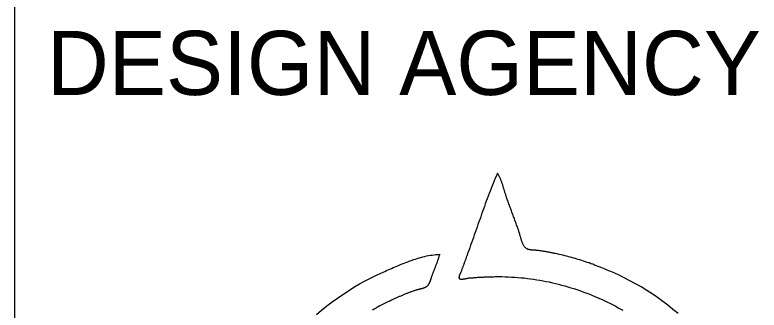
# Model space of a CAD drawing. Extents: x 0 to 34, y 0 to 22.
# Drawn here: x 32 to 33.162, y 4.514 to 4.975 of the extents above; entities that cross this region are included whole.
import ezdxf

# ---------------------------------------------------------------- set-up
doc = ezdxf.new("R2010")
doc.units = 0
for name, color, linetype in [('SH_Border', 7, 'Continuous'), ('SH_Data', 7, 'Continuous'), ('SH_Text', 7, 'Continuous')]:
    doc.layers.add(name, color=color, linetype=linetype)

msp = doc.modelspace()

# ---------------------------------------------------------------- linework, layer by layer
at = {"layer": 'SH_Border'}
msp.add_line((32, 0.5), (32, 21.5), dxfattribs=at)
at = {"layer": 'SH_Text'}
for points in [[(32.7532, 4.7277), (32.7515, 4.7238), (32.7498, 4.7199), (32.7481, 4.716), (32.7466, 4.712), (32.745, 4.708), (32.7434, 4.7041), (32.7418, 4.7001), (32.7403, 4.6961), (32.7387, 4.6921), (32.7372, 4.6881), (32.7357, 4.6841), (32.7342, 4.6801), (32.7328, 4.676), (32.7313, 4.672), (32.7298, 4.668), (32.7284, 4.6639), (32.7271, 4.6599), (32.7256, 4.6558), (32.7241, 4.6518), (32.7227, 4.6478), (32.7214, 4.6436), (32.7199, 4.6396), (32.7184, 4.6355), (32.7171, 4.6315), (32.7157, 4.6275), (32.7142, 4.6235), (32.7129, 4.6194), (32.7114, 4.6154), (32.71, 4.6114), (32.7085, 4.6074), (32.707, 4.6035)], [(32.7656, 4.6959), (32.7652, 4.6969), (32.7649, 4.6978), (32.7646, 4.6988), (32.7643, 4.6998), (32.764, 4.7009), (32.7637, 4.702), (32.7633, 4.7031), (32.7631, 4.7041), (32.7627, 4.7051), (32.7623, 4.7063), (32.7621, 4.7074), (32.7617, 4.7085), (32.7614, 4.7096), (32.761, 4.7107), (32.7606, 4.7118), (32.7603, 4.7129), (32.7599, 4.714), (32.7595, 4.7151), (32.7592, 4.7161), (32.7587, 4.7172), (32.7583, 4.7182), (32.7578, 4.7193), (32.7575, 4.7203), (32.757, 4.7214), (32.7565, 4.7223), (32.756, 4.7233), (32.7555, 4.7242), (32.7549, 4.7251), (32.7545, 4.726), (32.7538, 4.7268), (32.7532, 4.7277)], [(32.7856, 4.6404), (32.785, 4.6422), (32.7844, 4.644), (32.7837, 4.6457), (32.7831, 4.6475), (32.7823, 4.6493), (32.7817, 4.6512), (32.781, 4.6529), (32.7804, 4.6547), (32.7797, 4.6565), (32.7791, 4.6582), (32.7783, 4.66), (32.7777, 4.6618), (32.777, 4.6637), (32.7764, 4.6654), (32.7758, 4.6672), (32.7751, 4.669), (32.7745, 4.6708), (32.7739, 4.6725), (32.7731, 4.6743), (32.7725, 4.6761), (32.7719, 4.678), (32.7712, 4.6797), (32.7706, 4.6815), (32.77, 4.6833), (32.7694, 4.6851), (32.7686, 4.6869), (32.768, 4.6886), (32.7674, 4.6904), (32.7668, 4.6923), (32.7662, 4.6941), (32.7656, 4.6959)], [(32.7979, 4.6106), (32.7973, 4.6112), (32.7966, 4.6118), (32.796, 4.6124), (32.7954, 4.6131), (32.7949, 4.6138), (32.7943, 4.6147), (32.7939, 4.6156), (32.7934, 4.6165), (32.7929, 4.6175), (32.7925, 4.6186), (32.792, 4.6195), (32.7917, 4.6206), (32.7913, 4.6217), (32.7908, 4.6228), (32.7905, 4.6239), (32.7901, 4.6251), (32.7899, 4.6262), (32.7895, 4.6274), (32.7891, 4.6285), (32.7889, 4.6296), (32.7885, 4.6308), (32.7882, 4.6319), (32.7879, 4.633), (32.7877, 4.6341), (32.7873, 4.635), (32.7871, 4.636), (32.7868, 4.637), (32.7865, 4.638), (32.7862, 4.6388), (32.786, 4.6396), (32.7856, 4.6404)], [(32.5747, 4.5736), (32.5772, 4.5747), (32.5799, 4.5759), (32.5825, 4.577), (32.5852, 4.5782), (32.5879, 4.5794), (32.5907, 4.5806), (32.5934, 4.5818), (32.5962, 4.5829), (32.599, 4.5841), (32.6018, 4.5853), (32.6047, 4.5864), (32.6075, 4.5876), (32.6104, 4.5887), (32.6133, 4.5898), (32.6162, 4.5909), (32.6192, 4.5919), (32.6221, 4.593), (32.6251, 4.5938), (32.628, 4.5948), (32.6309, 4.5956), (32.6338, 4.5965), (32.6369, 4.5973), (32.6398, 4.5981), (32.6427, 4.5987), (32.6456, 4.5993), (32.6485, 4.5998), (32.6514, 4.6002), (32.6543, 4.6007), (32.6572, 4.601), (32.6601, 4.6012), (32.6629, 4.6015)], [(32.6629, 4.6015), (32.6626, 4.6002), (32.6623, 4.5992), (32.6619, 4.5979), (32.6616, 4.5969), (32.6612, 4.5958), (32.6609, 4.5945), (32.6605, 4.5935), (32.6601, 4.5922), (32.6596, 4.5912), (32.6593, 4.5901), (32.6589, 4.5888), (32.6584, 4.5878), (32.6581, 4.5867), (32.6576, 4.5856), (32.6572, 4.5844), (32.6567, 4.5833), (32.6564, 4.5822), (32.6559, 4.5811), (32.6555, 4.5799), (32.655, 4.5788), (32.6546, 4.5777), (32.6542, 4.5766), (32.6537, 4.5754), (32.6532, 4.5743), (32.6529, 4.5732), (32.6524, 4.5721), (32.652, 4.571), (32.6515, 4.5698), (32.6512, 4.5687), (32.6507, 4.5676), (32.6503, 4.5665)], [(32.707, 4.6035), (32.7067, 4.6025), (32.7063, 4.6016), (32.7061, 4.6006), (32.7057, 4.5996), (32.7054, 4.5987), (32.705, 4.5977), (32.7046, 4.5967), (32.7043, 4.5958), (32.7039, 4.5948), (32.7037, 4.5938), (32.7033, 4.5928), (32.7029, 4.592), (32.7026, 4.591), (32.7022, 4.5901), (32.7018, 4.5891), (32.7015, 4.5881), (32.7011, 4.5872), (32.7007, 4.5862), (32.7005, 4.5852), (32.7001, 4.5842), (32.6998, 4.5833), (32.6994, 4.5823), (32.699, 4.5813), (32.6987, 4.5804), (32.6983, 4.5795), (32.698, 4.5785), (32.6976, 4.5776), (32.6972, 4.5766), (32.6969, 4.5756), (32.6965, 4.5747), (32.6963, 4.5737)], [(32.8139, 4.6075), (32.8134, 4.6075), (32.8129, 4.6076), (32.8124, 4.6076), (32.8119, 4.6076), (32.8114, 4.6078), (32.8108, 4.6078), (32.8103, 4.6078), (32.8097, 4.6078), (32.8093, 4.6079), (32.8086, 4.6079), (32.808, 4.6079), (32.8076, 4.6079), (32.807, 4.608), (32.8063, 4.608), (32.8059, 4.6081), (32.8053, 4.6081), (32.8046, 4.6082), (32.8042, 4.6082), (32.8036, 4.6084), (32.8031, 4.6085), (32.8025, 4.6086), (32.802, 4.6087), (32.8015, 4.6089), (32.8009, 4.609), (32.8004, 4.6092), (32.7999, 4.6093), (32.7996, 4.6096), (32.7991, 4.6098), (32.7986, 4.6101), (32.7982, 4.6103), (32.7979, 4.6106)], [(32.8436, 4.6024), (32.8426, 4.6027), (32.8417, 4.6028), (32.8408, 4.603), (32.8398, 4.6033), (32.8388, 4.6034), (32.8379, 4.6036), (32.8369, 4.6038), (32.8359, 4.604), (32.835, 4.6041), (32.8341, 4.6044), (32.8331, 4.6045), (32.8322, 4.6047), (32.8312, 4.6049), (32.8302, 4.6051), (32.8293, 4.6052), (32.8283, 4.6055), (32.8273, 4.6056), (32.8263, 4.6057), (32.8254, 4.6059), (32.8244, 4.6061), (32.8234, 4.6062), (32.8225, 4.6063), (32.8215, 4.6065), (32.8205, 4.6067), (32.8196, 4.6068), (32.8186, 4.6069), (32.8177, 4.607), (32.8168, 4.6072), (32.8158, 4.6073), (32.8148, 4.6074), (32.8139, 4.6075)], [(32.9329, 4.5732), (32.9301, 4.5744), (32.9273, 4.5756), (32.9246, 4.5768), (32.9216, 4.5781), (32.9189, 4.5791), (32.9161, 4.5802), (32.9133, 4.5815), (32.9104, 4.5825), (32.9076, 4.5835), (32.9048, 4.5846), (32.9019, 4.5857), (32.8991, 4.5867), (32.8962, 4.5878), (32.8933, 4.5887), (32.8905, 4.5897), (32.8876, 4.5907), (32.8847, 4.5915), (32.8818, 4.5925), (32.8788, 4.5933), (32.8759, 4.5943), (32.873, 4.5952), (32.8701, 4.596), (32.8672, 4.5967), (32.8643, 4.5976), (32.8614, 4.5983), (32.8584, 4.599), (32.8554, 4.5998), (32.8525, 4.6005), (32.8495, 4.6012), (32.8466, 4.6018), (32.8436, 4.6024)], [(32.4709, 4.5076), (32.4788, 4.5143), (32.4868, 4.5207), (32.495, 4.5269), (32.5034, 4.533), (32.5119, 4.5388), (32.5205, 4.5445), (32.5292, 4.5498), (32.538, 4.555), (32.547, 4.56), (32.5561, 4.5647), (32.5653, 4.5693), (32.5747, 4.5736)], [(32.6503, 4.5665), (32.6501, 4.5661), (32.6499, 4.5656), (32.6498, 4.5652), (32.6496, 4.5647), (32.6495, 4.5642), (32.6493, 4.5638), (32.6492, 4.5631), (32.649, 4.5627), (32.6489, 4.5622), (32.6487, 4.5617), (32.6485, 4.5611), (32.6484, 4.5606), (32.6481, 4.5601), (32.648, 4.5595), (32.6478, 4.559), (32.6476, 4.5585), (32.6474, 4.5579), (32.6473, 4.5574), (32.647, 4.557), (32.6468, 4.5565), (32.6466, 4.556), (32.6463, 4.5555), (32.6461, 4.555), (32.6458, 4.5545), (32.6456, 4.5542), (32.6453, 4.5537), (32.6451, 4.5533), (32.6447, 4.553), (32.6445, 4.5525), (32.6441, 4.5521), (32.6438, 4.5519)], [(32.6963, 4.5737), (32.6961, 4.5735), (32.696, 4.5732), (32.6959, 4.573), (32.6958, 4.5727), (32.6957, 4.5724), (32.6955, 4.5721), (32.6954, 4.5718), (32.6952, 4.5714), (32.695, 4.571), (32.6949, 4.5707), (32.6947, 4.5703), (32.6946, 4.5699), (32.6944, 4.5696), (32.6942, 4.5691), (32.6941, 4.5687), (32.694, 4.5684), (32.6938, 4.568), (32.6937, 4.5675), (32.6936, 4.5671), (32.6935, 4.5668), (32.6935, 4.5664), (32.6933, 4.5661), (32.6933, 4.5657), (32.6932, 4.5653), (32.6932, 4.565), (32.6932, 4.5647), (32.6933, 4.5644), (32.6933, 4.5641), (32.6935, 4.5639), (32.6936, 4.5636), (32.6937, 4.5634)], [(32.7091, 4.5644), (32.7106, 4.5645), (32.7121, 4.5646), (32.7136, 4.5647), (32.7151, 4.5648), (32.7166, 4.565), (32.7181, 4.5651), (32.7195, 4.5652), (32.721, 4.5653), (32.7226, 4.5654), (32.724, 4.5656), (32.7255, 4.5657), (32.7269, 4.5657), (32.7285, 4.5658), (32.73, 4.5659), (32.7314, 4.5659), (32.7329, 4.5661), (32.7344, 4.5661), (32.7359, 4.5662), (32.7374, 4.5662), (32.7388, 4.5663), (32.7404, 4.5663), (32.7418, 4.5663), (32.7433, 4.5664), (32.7449, 4.5664), (32.7463, 4.5664), (32.7478, 4.5664), (32.7494, 4.5665), (32.7508, 4.5665), (32.7523, 4.5665), (32.7538, 4.5665), (32.7553, 4.5665)], [(32.7553, 4.5665), (32.7603, 4.5665), (32.7652, 4.5664), (32.7702, 4.5662), (32.7752, 4.5659), (32.7802, 4.5657), (32.785, 4.5653), (32.79, 4.5648), (32.7949, 4.5644), (32.7999, 4.5638), (32.8048, 4.5631), (32.8097, 4.5624), (32.8146, 4.5617), (32.8196, 4.5608), (32.8244, 4.56), (32.8293, 4.559), (32.8341, 4.5581), (32.839, 4.557), (32.8438, 4.5558), (32.8487, 4.5547), (32.8534, 4.5533), (32.8582, 4.552), (32.863, 4.5507), (32.8678, 4.5492), (32.8725, 4.5477), (32.8773, 4.5462), (32.882, 4.5446), (32.8866, 4.5429), (32.8913, 4.5412), (32.8959, 4.5394), (32.9005, 4.5376), (32.9052, 4.5357)], [(33.0351, 4.5088), (33.0272, 4.5154), (33.0194, 4.5217), (33.0112, 4.5277), (33.0031, 4.5337), (32.9947, 4.5394), (32.9863, 4.545), (32.9777, 4.5503), (32.9689, 4.5553), (32.9601, 4.5601), (32.9511, 4.5647), (32.942, 4.5691), (32.9329, 4.5732)], [(32.6937, 4.5634), (32.694, 4.5633), (32.6942, 4.563), (32.6946, 4.5629), (32.6949, 4.5628), (32.6954, 4.5627), (32.6958, 4.5627), (32.6963, 4.5625), (32.6967, 4.5625), (32.6973, 4.5625), (32.6978, 4.5625), (32.6984, 4.5625), (32.699, 4.5627), (32.6997, 4.5627), (32.7003, 4.5628), (32.7009, 4.5629), (32.7015, 4.563), (32.7021, 4.563), (32.7027, 4.5631), (32.7033, 4.5633), (32.7039, 4.5634), (32.7045, 4.5635), (32.705, 4.5636), (32.7056, 4.5638), (32.7062, 4.5639), (32.7067, 4.564), (32.7072, 4.5641), (32.7077, 4.5641), (32.708, 4.5642), (32.7085, 4.5644), (32.7087, 4.5644), (32.7091, 4.5644)], [(32.6259, 4.5453), (32.6248, 4.545), (32.6236, 4.5445), (32.6225, 4.5441), (32.6213, 4.5437), (32.6202, 4.5433), (32.6192, 4.5429), (32.6179, 4.5425), (32.6168, 4.5421), (32.6156, 4.5417), (32.6145, 4.5412), (32.6135, 4.5407), (32.6122, 4.5404), (32.6111, 4.5399), (32.6101, 4.5394), (32.6088, 4.539), (32.6078, 4.5385), (32.6067, 4.538), (32.6055, 4.5376), (32.6044, 4.5372), (32.6033, 4.5367), (32.6022, 4.5362), (32.601, 4.5357), (32.5999, 4.5353), (32.5988, 4.5348), (32.5977, 4.5343), (32.5966, 4.5338), (32.5955, 4.5333), (32.5944, 4.5328), (32.5932, 4.5324), (32.5921, 4.5317), (32.591, 4.5313)], [(32.6438, 4.5519), (32.6434, 4.5515), (32.6429, 4.5511), (32.6424, 4.5508), (32.6421, 4.5505), (32.6415, 4.5502), (32.641, 4.5499), (32.6405, 4.5497), (32.6399, 4.5493), (32.6393, 4.5491), (32.6387, 4.5488), (32.6381, 4.5487), (32.6375, 4.5485), (32.6369, 4.5482), (32.6362, 4.5481), (32.6356, 4.5479), (32.635, 4.5476), (32.6343, 4.5475), (32.6337, 4.5474), (32.6331, 4.5471), (32.6324, 4.547), (32.6318, 4.5469), (32.6312, 4.5467), (32.6305, 4.5465), (32.6299, 4.5464), (32.6293, 4.5463), (32.6287, 4.5461), (32.6281, 4.5459), (32.6275, 4.5458), (32.627, 4.5456), (32.6264, 4.5454), (32.6259, 4.5453)], [(32.591, 4.5313), (32.588, 4.5299), (32.585, 4.5284), (32.5819, 4.5269), (32.5789, 4.5254), (32.5759, 4.5239), (32.5728, 4.5223), (32.5698, 4.5207), (32.5669, 4.5191), (32.5639, 4.5174), (32.561, 4.5157), (32.558, 4.514)], [(32.9052, 4.5357), (32.9116, 4.533), (32.9179, 4.5302), (32.9242, 4.5271), (32.9305, 4.5241), (32.9367, 4.5208), (32.9427, 4.5174), (32.9488, 4.514)]]:
    msp.add_lwpolyline(points, dxfattribs=at)

# ---------------------------------------------------------------- texts
at = {"layer": 'SH_Data'}
msp.add_text('DESIGN AGENCY', height=0.1, dxfattribs=at).set_placement((32.05, 4.85))

doc.saveas('drawing.dxf')
